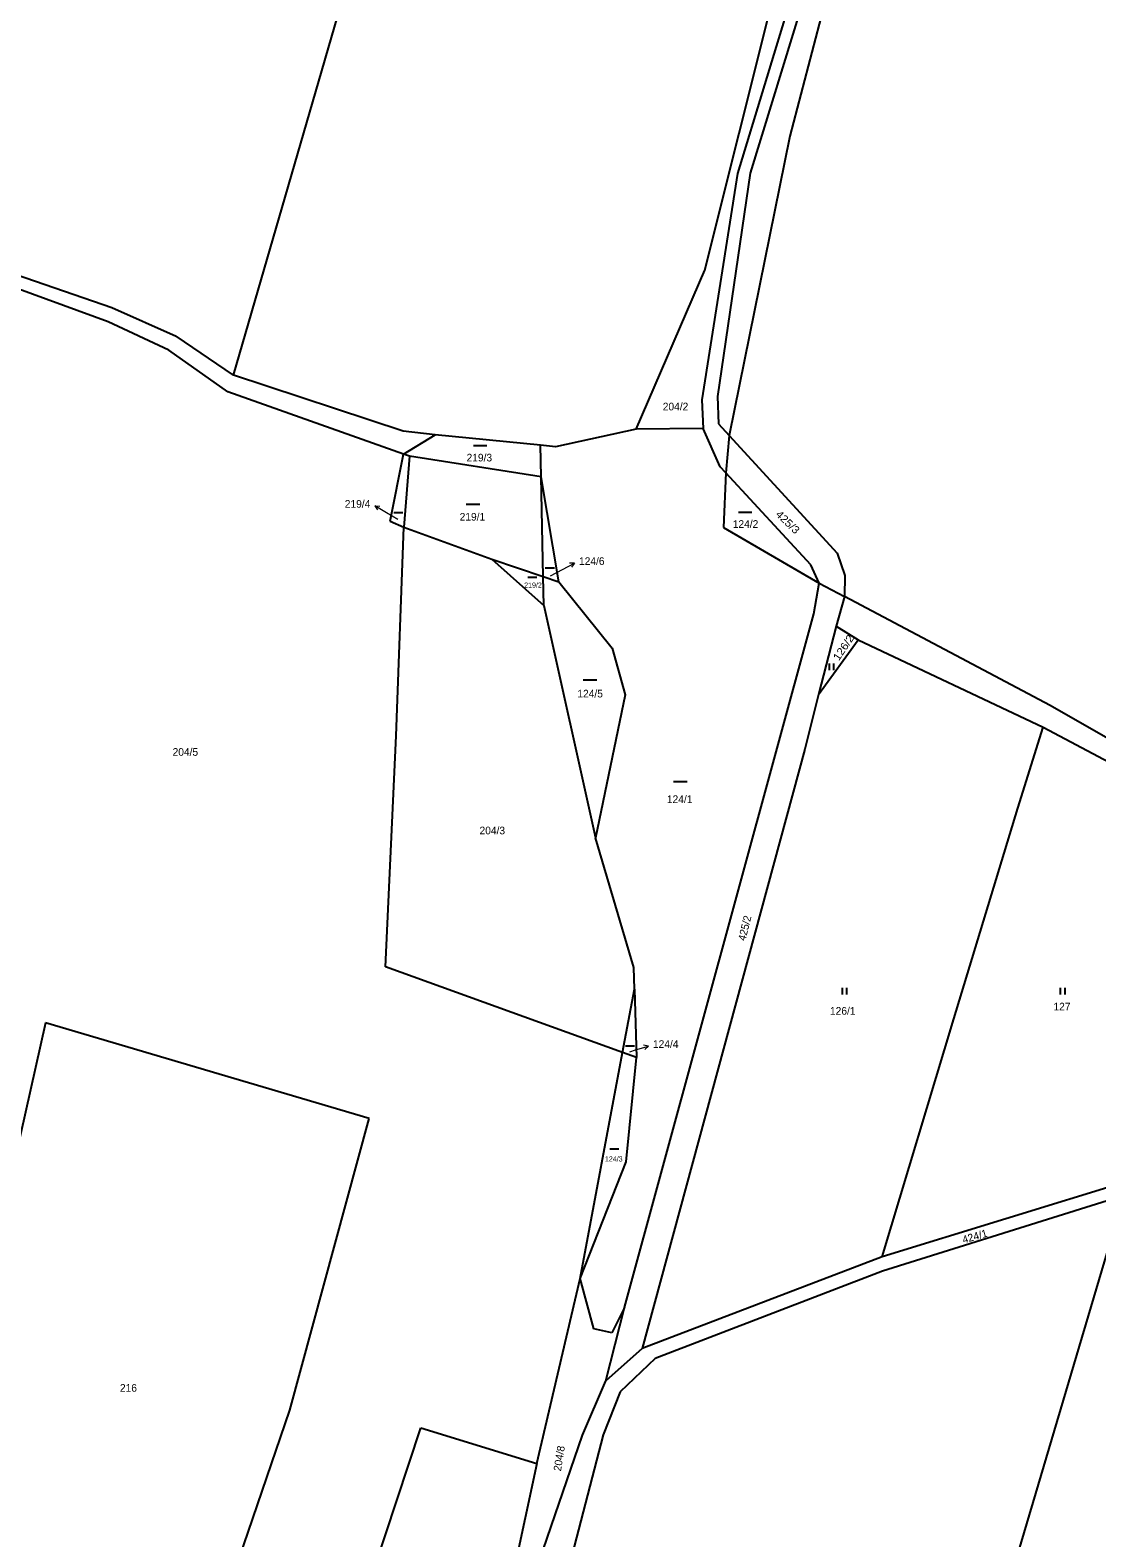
# Model space of a CAD drawing. Extents: x -791548 to -789311, y -1142631 to -1140855.
# Drawn here: x -790377.8 to -790140.3, y -1141959 to -1141623.3 of the extents above; entities that cross this region are included whole.
import ezdxf
from ezdxf.enums import TextEntityAlignment as Align

# ---------------------------------------------------------------- set-up
doc = ezdxf.new("R2010")
doc.units = 0
doc.header["$LTSCALE"] = 0.68
for name, color, linetype, lineweight in [('1', 7, 'Continuous', 25), ('3', 7, 'Continuous', 25), ('7', 7, 'Continuous', 13)]:
    doc.layers.add(name, color=color, linetype=linetype, lineweight=lineweight)
doc.layers.add('2', color=7, linetype='Continuous')

msp = doc.modelspace()

# ---------------------------------------------------------------- linework, layer by layer
at = {"layer": '1'}
for p, q in [((-790332.51, -1141700.08), (-790295.42, -1141572.35)), ((-790199.57, -1141586.79), (-790220.35, -1141655.18)), ((-790197.01, -1141588.1), (-790217.52, -1141655.12)), ((-790194.67, -1141593.52), (-790208.68, -1141646.83)), ((-790227.63, -1141676.68), (-790209.39, -1141603.99)), ((-790208.68, -1141646.83), (-790222.19, -1141713.51)), ((-790220.35, -1141655.18), (-790228.3, -1141705.55)), ((-790217.52, -1141655.12), (-790224.78, -1141704.83)), ((-790380.92, -1141677.66), (-790359.58, -1141685.03)), ((-790242.86, -1141712.11), (-790227.63, -1141676.68)), ((-790360.38, -1141688.22), (-790384.14, -1141679.55)), ((-790359.58, -1141685.03), (-790345.31, -1141691.42)), ((-790346.89, -1141694.53), (-790360.38, -1141688.22)), ((-790332.51, -1141700.08), (-790345.31, -1141691.42)), ((-790333.8, -1141703.82), (-790346.89, -1141694.53)), ((-790294.78, -1141712.55), (-790332.51, -1141700.08)), ((-790294.67, -1141717.66), (-790333.8, -1141703.82)), ((-790228.3, -1141705.55), (-790227.98, -1141711.96)), ((-790224.78, -1141704.83), (-790224.54, -1141710.95)), ((-790287.59, -1141713.38), (-790294.78, -1141712.55)), ((-790242.86, -1141712.11), (-790260.83, -1141716.02)), ((-790227.98, -1141711.96), (-790242.86, -1141712.11)), ((-790224.16, -1141720.49), (-790227.98, -1141711.96)), ((-790224.54, -1141710.95), (-790222.19, -1141713.51)), ((-790294.67, -1141717.66), (-790287.59, -1141713.38)), ((-790260.83, -1141716.02), (-790264.16, -1141715.69)), ((-790222.19, -1141713.51), (-790222.93, -1141721.83)), ((-790222.19, -1141713.51), (-790198.16, -1141739.76)), ((-790297.65, -1141732.62), (-790294.67, -1141717.66)), ((-790293.34, -1141718.13), (-790294.67, -1141717.66)), ((-790293.34, -1141718.13), (-790294.61, -1141733.91)), ((-790264.06, -1141722.75), (-790293.34, -1141718.13)), ((-790263.56, -1141744.95), (-790264.06, -1141722.75)), ((-790260.09, -1141746.13), (-790264.06, -1141722.75)), ((-790222.93, -1141721.83), (-790224.16, -1141720.49)), ((-790222.93, -1141721.83), (-790223.44, -1141733.98)), ((-790204, -1141742.32), (-790222.93, -1141721.83)), ((-790297.65, -1141732.62), (-790294.61, -1141733.91)), ((-790296.34, -1141780.39), (-790294.61, -1141733.91)), ((-790294.61, -1141733.91), (-790275.03, -1141741.04)), ((-790223.44, -1141733.98), (-790202.13, -1141746.39)), ((-790198.16, -1141739.76), (-790196.43, -1141744.7)), ((-790275.03, -1141741.04), (-790263.41, -1141751.4)), ((-790275.03, -1141741.04), (-790263.56, -1141744.95)), ((-790202.13, -1141746.39), (-790204, -1141742.32)), ((-790263.41, -1141751.4), (-790263.56, -1141744.95)), ((-790263.56, -1141744.95), (-790260.09, -1141746.13)), ((-790260.09, -1141746.13), (-790248.22, -1141760.88)), ((-790203.32, -1141753.24), (-790202.13, -1141746.39)), ((-790202.13, -1141746.39), (-790196.53, -1141749.35)), ((-790196.43, -1141744.7), (-790196.53, -1141749.35)), ((-790196.53, -1141749.35), (-790198.35, -1141755.99)), ((-790150.73, -1141773.63), (-790196.53, -1141749.35)), ((-790263.41, -1141751.4), (-790251.91, -1141803.09)), ((-790245.47, -1141907.71), (-790203.32, -1141753.24)), ((-790198.35, -1141755.99), (-790202.27, -1141771.23)), ((-790198.35, -1141755.99), (-790193.47, -1141758.99)), ((-790202.27, -1141771.23), (-790193.47, -1141758.99)), ((-790193.47, -1141758.99), (-790152.3, -1141778.49)), ((-790248.22, -1141760.88), (-790245.3, -1141771.26)), ((-790245.3, -1141771.26), (-790251.91, -1141803.09)), ((-790202.27, -1141771.23), (-790205.35, -1141783.36)), ((-790115.83, -1141793.73), (-790150.73, -1141773.63)), ((-790157.91, -1141796.53), (-790152.3, -1141778.49)), ((-790152.3, -1141778.49), (-790116.76, -1141797.27)), ((-790298.7, -1141831.83), (-790296.34, -1141780.39)), ((-790205.35, -1141783.36), (-790241.57, -1141916.85)), ((-790172.19, -1141843.44), (-790157.91, -1141796.53)), ((-790243.4, -1141831.99), (-790251.91, -1141803.09)), ((-790245.9, -1141850.91), (-790298.7, -1141831.83)), ((-790243.25, -1141836.84), (-790243.4, -1141831.99)), ((-790245.9, -1141850.91), (-790243.25, -1141836.84)), ((-790243.25, -1141836.84), (-790242.78, -1141852.04)), ((-790188.11, -1141896.44), (-790172.19, -1141843.44)), ((-790374.35, -1141844.29), (-790389.94, -1141913.7)), ((-790302.33, -1141865.59), (-790374.35, -1141844.29)), ((-790255.37, -1141901.24), (-790245.9, -1141850.91)), ((-790242.78, -1141852.04), (-790245.9, -1141850.91)), ((-790245.14, -1141875.24), (-790242.78, -1141852.04)), ((-790319.97, -1141930.59), (-790302.33, -1141865.59)), ((-790255.37, -1141901.24), (-790245.14, -1141875.24)), ((-790133.08, -1141879.48), (-790188.11, -1141896.44)), ((-790134.26, -1141882.79), (-790188.03, -1141899.6)), ((-790157.72, -1141961.89), (-790134.26, -1141882.79)), ((-790188.11, -1141896.44), (-790241.57, -1141916.85)), ((-790188.03, -1141899.6), (-790238.62, -1141919.07)), ((-790264.99, -1141942.42), (-790255.37, -1141901.24)), ((-790252.33, -1141912.46), (-790255.37, -1141901.24)), ((-790249.62, -1141924.04), (-790245.47, -1141907.71)), ((-790245.47, -1141907.71), (-790248.3, -1141913.35)), ((-790248.3, -1141913.35), (-790252.33, -1141912.46)), ((-790241.57, -1141916.85), (-790249.62, -1141924.04)), ((-790238.62, -1141919.07), (-790246.41, -1141926.52)), ((-790254.81, -1141936.13), (-790249.62, -1141924.04)), ((-790246.41, -1141926.52), (-790250.25, -1141936.04)), ((-790342.92, -1141997.77), (-790319.97, -1141930.59)), ((-790303.39, -1141972.55), (-790290.79, -1141934.53)), ((-790290.79, -1141934.53), (-790264.99, -1141942.42)), ((-790268.79, -1141976.64), (-790254.81, -1141936.13)), ((-790250.25, -1141936.04), (-790259.72, -1141972.52)), ((-790264.99, -1141942.42), (-790270.6, -1141968.43))]:
    msp.add_line(p, q, dxfattribs=at)
msp.add_lwpolyline([(-790264.06, -1141722.75), (-790264.16, -1141715.69), (-790287.59, -1141713.38)], dxfattribs=at)
at = {"layer": '3'}
for p, q in [((-790279.098, -1141715.78), (-790276.098, -1141715.78)), ((-790280.708, -1141728.8), (-790277.708, -1141728.8)), ((-790296.854, -1141730.64), (-790294.844, -1141730.64)), ((-790220.108, -1141730.63), (-790217.108, -1141730.63)), ((-790263.104, -1141743.01), (-790261.094, -1141743.01)), ((-790267.034, -1141745.08), (-790265.024, -1141745.08)), ((-790199.881, -1141765.77), (-790199.881, -1141764.27)), ((-790198.88, -1141765.77), (-790198.88, -1141764.27)), ((-790254.648, -1141767.93), (-790251.648, -1141767.93)), ((-790234.538, -1141790.59), (-790231.538, -1141790.59)), ((-790196.971, -1141838.02), (-790196.971, -1141836.52)), ((-790195.97, -1141838.02), (-790195.97, -1141836.52)), ((-790148.411, -1141838.03), (-790148.411, -1141836.53)), ((-790147.41, -1141838.03), (-790147.41, -1141836.53)), ((-790245.264, -1141849.47), (-790243.254, -1141849.47)), ((-790248.724, -1141872.36), (-790246.714, -1141872.36))]:
    msp.add_line(p, q, dxfattribs=at)
at = {"layer": '7'}
for p, q in [((-790301.052, -1141729.164), (-790300.452, -1141730.109)), ((-790256.61, -1141741.921), (-790257.73, -1141741.949)), ((-790240.15, -1141849.473), (-790241.254, -1141849.287))]:
    msp.add_line(p, q, dxfattribs=at)
for points in [[(-790295.93, -1141732.22), (-790298.48, -1141730.71), (-790301.052, -1141729.164), (-790299.936, -1141729.251)], [(-790261.96, -1141744.76), (-790259.26, -1141743.33), (-790256.61, -1141741.921), (-790257.259, -1141742.833)], [(-790244.28, -1141850.74), (-790243.02, -1141850.35), (-790240.15, -1141849.473), (-790240.961, -1141850.244)]]:
    msp.add_lwpolyline(points, dxfattribs=at)

# ---------------------------------------------------------------- texts
at = {"layer": '2'}
for s, height, p in [('204/2', 1.7, (-790234.12, -1141707.922)), ('219/3', 1.7, (-790277.79, -1141719.295)), ('219/1', 1.7, (-790279.33, -1141732.472)), ('124/2', 1.7, (-790218.54, -1141734.085)), ('219/2', 1.14, (-790265.849, -1141747.405)), ('124/5', 1.7, (-790253.13, -1141771.852)), ('204/5', 1.7, (-790343.23, -1141784.842)), ('124/1', 1.7, (-790233.2, -1141795.362)), ('204/3', 1.7, (-790274.91, -1141802.332)), ('127', 1.7, (-790148.099, -1141841.552)), ('126/1', 1.7, (-790196.9, -1141842.502)), ('124/3', 1.14, (-790247.869, -1141875.185)), ('216', 1.7, (-790355.899, -1141926.462))]:
    msp.add_text(s, height=height, dxfattribs=at).set_placement(p, align=Align.CENTER)
msp.add_text('219/4', height=1.7, dxfattribs=at).set_placement((-790302.06, -1141729.605), align=Align.RIGHT)
at = {"layer": '2', "width": 1.1}
for s, rotation, p in [('425/3', 316, (-790209.7305, -1141733.4222)), ('126/2', 56, (-790196.0225, -1141761.2243))]:
    msp.add_text(s, height=1.7, rotation=rotation, dxfattribs=at).set_placement(p, align=Align.CENTER)
at = {"layer": '2'}
for s, p in [('124/6', (-790255.61, -1141742.345)), ('124/4', (-790239.15, -1141849.895))]:
    msp.add_text(s, height=1.7, dxfattribs=at).set_placement(p)
for s, rotation, p in [('425/2', 76, (-790217.8988, -1141823.4256)), ('424/1', 16, (-790167.2763, -1141892.688)), ('204/8', 81, (-790259.1816, -1141941.452))]:
    msp.add_text(s, height=1.7, rotation=rotation, dxfattribs=at).set_placement(p, align=Align.CENTER)

doc.saveas('drawing.dxf')
